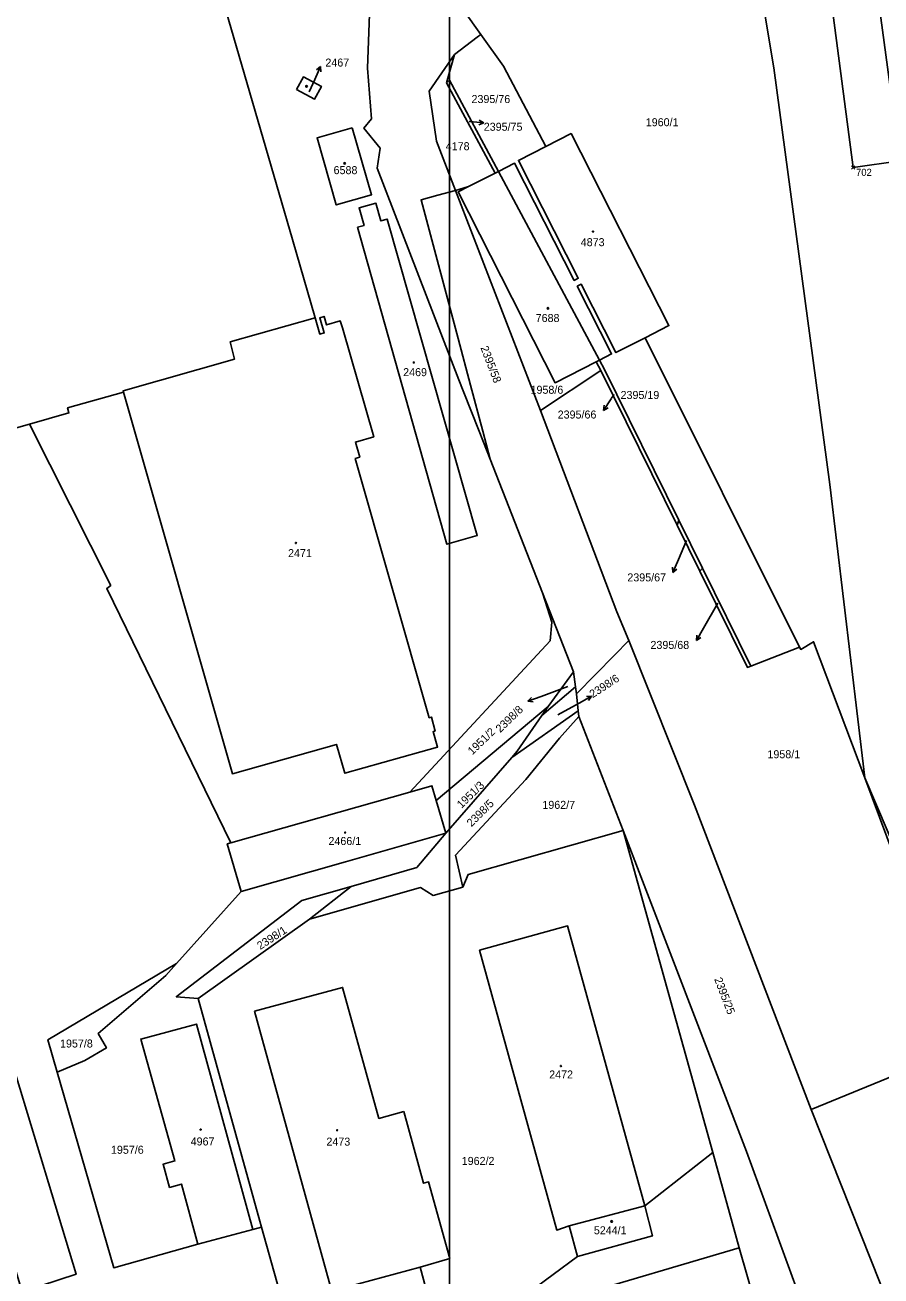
# Model space of a CAD drawing. Extents: x -667048 to -665920, y -1108425 to -1107247.
# Drawn here: x -666928.5 to -666746.8, y -1107866.2 to -1107600.6 of the extents above; entities that cross this region are included whole.
import ezdxf

# ---------------------------------------------------------------- set-up
doc = ezdxf.new("R2010")
doc.units = 0
for name, color, linetype in [('_JC - Obvod stavby - Přesunutá', 7, 'Continuous'), ('Default', 7, 'Continuous'), ('Hranice parcel', 7, 'Continuous'), ('Parcelní čísla', 7, 'Continuous'), ('Pop_ PČ_ popisy', 7, 'Continuous'), ('RK-body obvod stavby docasny zabor', 7, 'Continuous'), ('Vrstva 2', 7, 'Continuous'), ('Značky budov', 7, 'Continuous')]:
    doc.layers.add(name, color=color, linetype=linetype)

# ---------------------------------------------------------------- blocks, each defined once
blk = doc.blocks.new('4.021')
at = {"layer": 'Default'}
blk.add_circle((-7, 1), 175, dxfattribs=at)
blk = doc.blocks.new('10291')
at = {"layer": 'Default'}
for p, q in [((0, 3001), (-500, 2001)), ((0, 1), (0, 3001)), ((0, 3001), (500, 2001))]:
    blk.add_line(p, q, dxfattribs=at)
blk = doc.blocks.new('POINT_DISPLAY')
at = {"layer": 'Default'}
for p, q in [((-354, 354), (354, -354)), ((354, 354), (-354, -354))]:
    blk.add_line(p, q, dxfattribs=at)

msp = doc.modelspace()

# ---------------------------------------------------------------- linework, layer by layer
at = {"layer": '_JC - Obvod stavby - Přesunutá'}
msp.add_lwpolyline([(-666742.73, -1107629.44), (-666752.71, -1107630.84), (-666760.26, -1107573.13), (-666748.86, -1107584.37)], close=True, dxfattribs=at)
at = {"layer": 'Hranice parcel'}
for points in [[(-666750.22, -1107760.47), (-666757.71, -1107698.17), (-666769.58, -1107609.67), (-666782.23, -1107534.06), (-666786.44, -1107529.88), (-666794.82, -1107524.4)], [(-666892.11, -1107576.02), (-666871.77, -1107646.16), (-666866.96, -1107662.76)], [(-666846.81, -1107581.36), (-666831.75, -1107602.59)], [(-666836.41, -1107675.92), (-666853.77, -1107631.04), (-666853.14, -1107626.74), (-666856.57, -1107622.48), (-666854.99, -1107620.56), (-666855.81, -1107609.79), (-666855.32, -1107596.36), (-666856.63, -1107586.11)], [(-666837.32, -1107606.86), (-666832.53, -1107603.19), (-666831.75, -1107602.59)], [(-666831.75, -1107602.59), (-666826.97, -1107609.33)], [(-666841.15, -1107625.29), (-666842.71, -1107614.67), (-666837.32, -1107606.86)], [(-666839.02, -1107612.88), (-666837.32, -1107606.86)], [(-666826.97, -1107609.33), (-666817.96, -1107626.38)], [(-666870.88, -1107614.29), (-666869.41, -1107611.62), (-666865.61, -1107613.66), (-666867.08, -1107616.36), (-666870.88, -1107614.29)], [(-666839.02, -1107612.88), (-666838.38, -1107612.29), (-666828.04, -1107631.71)], [(-666828.74, -1107632.07), (-666839.02, -1107612.88)], [(-666859.04, -1107622.45), (-666854.97, -1107636.66), (-666862.46, -1107638.81), (-666866.53, -1107624.59), (-666859.04, -1107622.45)], [(-666817.96, -1107626.38), (-666812.62, -1107623.65), (-666791.85, -1107664.44), (-666796.91, -1107667.02)], [(-666837.13, -1107635.72), (-666841.15, -1107625.29)], [(-666817.96, -1107626.38), (-666823.78, -1107629.37), (-666811.07, -1107654.39), (-666811.92, -1107654.85), (-666824.58, -1107629.95), (-666828.04, -1107631.71)], [(-666828.04, -1107631.71), (-666828.74, -1107632.07)], [(-666828.04, -1107631.71), (-666806.59, -1107671.77)], [(-666828.74, -1107632.07), (-666834.38, -1107634.93)], [(-666829.79, -1107692.78), (-666831.36, -1107686.82), (-666833.92, -1107677.11), (-666836.55, -1107667.14), (-666844.44, -1107637.74), (-666840.87, -1107636.75), (-666837.13, -1107635.72)], [(-666834.38, -1107634.93), (-666837.13, -1107635.72)], [(-666837.13, -1107635.72), (-666819.12, -1107682.43)], [(-666807.28, -1107672.12), (-666816.01, -1107676.57), (-666836.59, -1107636.06), (-666834.38, -1107634.93)], [(-666857.92, -1107643.53), (-666856.56, -1107643.16), (-666857.61, -1107639.44), (-666854.03, -1107638.47), (-666852.98, -1107642.19), (-666851.62, -1107641.82), (-666832.53, -1107708.98), (-666839, -1107710.87), (-666857.92, -1107643.53)], [(-666796.91, -1107667.02), (-666803.07, -1107670.15), (-666810.43, -1107655.65), (-666811.31, -1107656.08), (-666804, -1107670.45), (-666806.59, -1107671.77)], [(-666907.63, -1107678.59), (-666907.71, -1107678.31), (-666884.06, -1107671.56), (-666884.97, -1107667.91), (-666866.96, -1107662.76)], [(-666866.96, -1107662.76), (-666865.96, -1107666.25), (-666865, -1107666), (-666865.94, -1107662.76), (-666865.05, -1107662.5), (-666864.53, -1107664.28), (-666861.59, -1107663.44), (-666861.15, -1107664.89), (-666854.49, -1107688.05), (-666858.38, -1107689.17), (-666857.47, -1107692.36), (-666858.43, -1107692.64), (-666842.72, -1107747.72), (-666842.26, -1107747.58), (-666841.46, -1107750.53), (-666841.89, -1107750.66), (-666840.96, -1107753.94), (-666844.51, -1107754.94), (-666860.6, -1107759.49), (-666862.42, -1107753.35), (-666884.5, -1107759.61), (-666907.63, -1107678.59)], [(-666796.91, -1107667.02), (-666764.09, -1107732.71)], [(-666806.3, -1107673.95), (-666819.12, -1107682.43)], [(-666807.28, -1107672.12), (-666806.59, -1107671.77)], [(-666806.3, -1107673.95), (-666807.28, -1107672.12)], [(-666806.59, -1107671.77), (-666805.5, -1107673.78), (-666789.73, -1107705.73)], [(-666790.1, -1107706.79), (-666806.3, -1107673.95)], [(-666829.79, -1107692.78), (-666832.12, -1107686.83), (-666835.48, -1107678.28), (-666836.41, -1107675.92)], [(-666907.63, -1107678.59), (-666919.5, -1107681.91), (-666919.19, -1107682.99), (-666927.58, -1107685.38)], [(-666819.12, -1107682.43), (-666802.87, -1107725.2), (-666800.32, -1107731.32)], [(-666927.58, -1107685.38), (-666970.29, -1107697.51), (-666970.95, -1107695.22)], [(-666927.58, -1107685.38), (-666910.31, -1107719.61), (-666911.16, -1107720.23), (-666884.82, -1107774.29)], [(-666818.65, -1107721.17), (-666829.79, -1107692.78)], [(-666790.1, -1107706.79), (-666789.73, -1107705.73)], [(-666789.73, -1107705.73), (-666784.7, -1107715.92)], [(-666785.28, -1107716.56), (-666790.1, -1107706.79)], [(-666785.28, -1107716.56), (-666784.7, -1107715.92)], [(-666774.43, -1107736.74), (-666775.18, -1107737.03), (-666785.28, -1107716.56)], [(-666784.7, -1107715.92), (-666774.43, -1107736.74)], [(-666817.01, -1107731.37), (-666816.71, -1107727.4), (-666818.65, -1107721.17)], [(-666812.06, -1107737.98), (-666818.65, -1107721.17)], [(-666846.86, -1107763.48), (-666817.01, -1107731.37)], [(-666800.32, -1107731.32), (-666803.36, -1107734.4), (-666811.44, -1107742.6)], [(-666800.32, -1107731.32), (-666786.38, -1107766.3), (-666761.63, -1107830.87)], [(-666750.22, -1107760.47), (-666761.12, -1107731.55), (-666763.85, -1107733.2), (-666764.09, -1107732.71)], [(-666764.09, -1107732.71), (-666774.43, -1107736.74)], [(-666817.49, -1107745.32), (-666812.06, -1107737.98)], [(-666812.06, -1107737.98), (-666811.64, -1107741.12)], [(-666811.64, -1107741.12), (-666818.79, -1107747.22)], [(-666811.44, -1107742.6), (-666811.64, -1107741.12)], [(-666811.44, -1107742.6), (-666811.08, -1107746.21)], [(-666841.22, -1107765.27), (-666817.49, -1107745.32)], [(-666818.79, -1107747.22), (-666817.49, -1107745.32)], [(-666810.96, -1107747.47), (-666815.09, -1107752.06), (-666822.19, -1107760.79), (-666837.12, -1107776.86), (-666835.58, -1107783.69)], [(-666811.08, -1107746.21), (-666825.18, -1107756.15)], [(-666825.18, -1107756.15), (-666824.02, -1107754.82), (-666818.79, -1107747.22)], [(-666811.08, -1107746.21), (-666810.96, -1107747.47)], [(-666810.96, -1107747.47), (-666801.53, -1107771.67)], [(-666839.17, -1107772.23), (-666825.18, -1107756.15)], [(-666730.73, -1107818.25), (-666727.95, -1107817.11), (-666741.44, -1107784.12), (-666742.49, -1107781.31), (-666750.22, -1107760.47)], [(-666705.91, -1107864.42), (-666750.22, -1107760.47)], [(-666884.82, -1107774.29), (-666846.86, -1107763.48)], [(-666841.22, -1107765.27), (-666842.15, -1107762.14), (-666846.86, -1107763.48)], [(-666839.17, -1107772.23), (-666841.22, -1107765.27)], [(-666839.17, -1107772.23), (-666856.55, -1107777.18), (-666860.49, -1107778.3), (-666882.64, -1107784.61)], [(-666845.34, -1107779.48), (-666839.17, -1107772.23)], [(-666801.53, -1107771.67), (-666834.43, -1107780.97), (-666835.58, -1107783.69)], [(-666752.66, -1107901.06), (-666760.59, -1107880.31), (-666775.34, -1107839.8), (-666801.53, -1107771.67)], [(-666782.54, -1107840.04), (-666801.53, -1107771.67)], [(-666882.64, -1107784.61), (-666885.59, -1107774.51), (-666884.82, -1107774.29)], [(-666859.3, -1107783.51), (-666845.34, -1107779.48)], [(-666891.76, -1107807.33), (-666896.41, -1107806.95), (-666869.79, -1107786.54), (-666859.3, -1107783.51)], [(-666896.35, -1107799.89), (-666882.64, -1107784.61)], [(-666868.13, -1107790.45), (-666859.3, -1107783.51)], [(-666835.58, -1107783.69), (-666841.85, -1107785.42), (-666844.6, -1107783.77), (-666868.13, -1107790.45)], [(-666868.13, -1107790.45), (-666891.76, -1107807.33)], [(-666813.02, -1107855.57), (-666815.66, -1107856.49), (-666832.04, -1107797.07), (-666813.36, -1107791.92), (-666796.98, -1107851.34)], [(-666921.72, -1107822.93), (-666923.71, -1107816.1), (-666896.35, -1107799.89)], [(-666896.35, -1107799.89), (-666898.64, -1107802.46)], [(-666898.64, -1107802.46), (-666913.02, -1107814.76), (-666911.25, -1107817.81), (-666915.86, -1107820.51), (-666921.72, -1107822.93)], [(-666879.8, -1107810.04), (-666861.1, -1107804.96), (-666853.4, -1107832.79), (-666848.11, -1107831.33)], [(-666878.29, -1107855.87), (-666878.65, -1107854.58), (-666891.76, -1107807.33)], [(-666862.97, -1107869.35), (-666863.4, -1107869.55), (-666879.8, -1107810.04)], [(-666891.86, -1107859.5), (-666895.33, -1107846.72), (-666897.82, -1107847.42), (-666899.21, -1107842.51), (-666896.7, -1107841.82), (-666903.94, -1107815.93), (-666892.15, -1107812.76), (-666880.19, -1107856.38)], [(-666761.63, -1107830.87), (-666730.73, -1107818.25)], [(-666942.5, -1107825.4), (-666931.02, -1107821.66), (-666917.67, -1107865.87), (-666929.14, -1107869.61), (-666942.5, -1107825.4)], [(-666891.86, -1107859.5), (-666909.68, -1107864.48), (-666921.72, -1107822.93)], [(-666742.75, -1107878.49), (-666761.63, -1107830.87)], [(-666848.11, -1107831.33), (-666843.92, -1107846.55), (-666842.86, -1107846.25), (-666838.36, -1107862.54), (-666844.66, -1107864.39)], [(-666796.98, -1107851.34), (-666782.54, -1107840.04)], [(-666782.54, -1107840.04), (-666776.91, -1107860.29)], [(-666813.02, -1107855.57), (-666796.98, -1107851.34)], [(-666796.98, -1107851.34), (-666795.32, -1107857.74), (-666811.21, -1107862.12)], [(-666880.19, -1107856.38), (-666891.86, -1107859.5)], [(-666878.29, -1107855.87), (-666880.19, -1107856.38)], [(-666864.97, -1107903.57), (-666878.29, -1107855.87)], [(-666811.21, -1107862.12), (-666813.02, -1107855.57)], [(-666821.56, -1107869.77), (-666811.21, -1107862.12)], [(-666790.1, -1107954.73), (-666790.14, -1107954.57), (-666813.39, -1107871), (-666776.91, -1107860.29)], [(-666776.91, -1107860.29), (-666770.16, -1107883.94)], [(-666844.66, -1107864.39), (-666842.92, -1107870.69), (-666861.2, -1107875.75), (-666862.97, -1107869.35)], [(-666862.97, -1107869.35), (-666844.66, -1107864.39)]]:
    msp.add_lwpolyline(points, dxfattribs=at)
at = {"layer": 'Pop_ PČ_ popisy'}
for points in [[(-666868.17, -1107614.78), (-666866.99, -1107612.17)], [(-666834.24, -1107621.1), (-666834.13, -1107621.11)], [(-666803.47, -1107679.04), (-666804.06, -1107679.95)], [(-666788.1, -1107710.04), (-666789.8, -1107714.09)], [(-666781.42, -1107723.35), (-666784.46, -1107728.71)], [(-666813.28, -1107741.09), (-666818.96, -1107743.17)], [(-666815.39, -1107747.11), (-666810.87, -1107744.58)]]:
    msp.add_lwpolyline(points, dxfattribs=at)
at = {"layer": 'Vrstva 2'}
msp.add_lwpolyline([(-666838.39, -1107343.37), (-666244.39, -1107343.37), (-666244.39, -1108183.37), (-666838.39, -1108183.37)], close=True, dxfattribs=at)

# ---------------------------------------------------------------- block references
at = {"layer": 'Pop_ PČ_ popisy'}
for p, xscale, yscale, rotation in [((-666866.99, -1107612.17), 0.0010000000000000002, 0.0010000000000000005, -23.99999999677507), ((-666834.13, -1107621.11), 0.0010000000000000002, 0.0010000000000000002, -94.99999999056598), ((-666804.06, -1107679.95), 0.0010000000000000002, 0.0010000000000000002, 147.0000000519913), ((-666789.8, -1107714.09), 0.0010000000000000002, 0.001, 157.0000000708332), ((-666784.46, -1107728.71), 0.0010000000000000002, 0.0010000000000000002, 149.99999996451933), ((-666818.96, -1107743.17), 0.0010000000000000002, 0.001, 109.99999998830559), ((-666810.87, -1107744.58), 0.001, 0.0010000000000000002, -61.00000001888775)]:
    msp.add_blockref('10291', p, dxfattribs=dict(at, xscale=xscale, yscale=yscale, rotation=rotation))
at = {"layer": 'RK-body obvod stavby docasny zabor', "xscale": 0.0010000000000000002, "yscale": 0.0010000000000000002}
msp.add_blockref('POINT_DISPLAY', (-666752.71, -1107630.84), dxfattribs=at)
at = {"layer": 'Značky budov'}
for p, xscale, yscale in [((-666868.76, -1107613.64), 0.0010000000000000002, 0.0010000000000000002), ((-666860.66, -1107629.98), 0.0010000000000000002, 0.0010000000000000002), ((-666807.95, -1107644.47), 0.0006700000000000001, 0.0006700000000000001), ((-666817.49, -1107660.76), 0.0010000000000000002, 0.0010000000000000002), ((-666845.97, -1107672.26), 0.0006700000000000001, 0.0006700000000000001), ((-666871.01, -1107710.61), 0.0006700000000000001, 0.0006700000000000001), ((-666860.56, -1107772.09), 0.0006700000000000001, 0.0006700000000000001), ((-666814.76, -1107821.65), 0.0006700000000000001, 0.0006700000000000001), ((-666891.22, -1107835.16), 0.0006700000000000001, 0.0006700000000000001), ((-666862.25, -1107835.3), 0.0006700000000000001, 0.0006700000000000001), ((-666803.97, -1107854.66), 0.0010000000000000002, 0.0010000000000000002)]:
    msp.add_blockref('4.021', p, dxfattribs=dict(at, xscale=xscale, yscale=yscale))

# ---------------------------------------------------------------- texts
at = {"layer": 'Parcelní čísla'}
for s, p in [('2467', (-666864.76, -1107609.43)), ('2395/76', (-666833.74, -1107617.18)), ('1960/1', (-666796.75, -1107622.1)), ('2395/75', (-666831.14, -1107623.06)), ('4178', (-666839.21, -1107627.19)), ('6588', (-666863.02, -1107632.28)), ('4873', (-666810.55, -1107647.57)), ('7688', (-666820.12, -1107663.67)), ('2469', (-666848.25, -1107675.17)), ('1958/6', (-666821.21, -1107678.91)), ('2395/19', (-666802.1, -1107680.02)), ('2395/66', (-666815.45, -1107684.17)), ('2471', (-666872.69, -1107713.6)), ('2395/67', (-666800.66, -1107718.75)), ('2395/68', (-666795.75, -1107733.09)), ('1958/1', (-666770.92, -1107756.3)), ('1962/7', (-666818.7, -1107767.05)), ('2466/1', (-666864.11, -1107774.73)), ('1957/8', (-666921.09, -1107817.73)), ('2472', (-666817.25, -1107824.3)), ('1957/6', (-666910.28, -1107840.29)), ('4967', (-666893.36, -1107838.52)), ('2473', (-666864.54, -1107838.56)), ('1962/2', (-666835.82, -1107842.66)), ('5244/1', (-666807.77, -1107857.39))]:
    msp.add_text(s, height=1.7, dxfattribs=at).set_placement(p)
for s, rotation, p in [('2395/58', 291, (-666831.87, -1107669.13)), ('2398/6', 33, (-666808.02, -1107743.58)), ('2398/8', 44, (-666827.64, -1107750.98)), ('1951/2', 44, (-666833.55, -1107755.7)), ('1951/3', 44, (-666835.87, -1107767.06)), ('2398/5', 45, (-666833.75, -1107770.99)), ('2398/1', 33, (-666878.59, -1107797.03)), ('2395/25', 291, (-666782.25, -1107803.21))]:
    msp.add_text(s, height=1.7, rotation=rotation, dxfattribs=at).set_placement(p)
at = {"layer": 'RK-body obvod stavby docasny zabor'}
msp.add_text('702', height=1.5, dxfattribs=at).set_placement((-666752.11, -1107632.64))

doc.saveas('drawing.dxf')
